(* Logix 5000 project; controller Soda_Ash vendor 1 type 14 code 92 rev 35.11; software revision 35.00 *)

TASK MainTask (continuous, watchdog 500 ms) : MainProgram, Simulation, Soda_Ash

MODULES
   Local : vendor 1 type 14 code 92 (ICP 5, rev 35.11)
      abclogixio3 : 1756-ENBT (ICP 9, Ethernet 131.151.52.140, rev 4.3)
         abclogixio2 : 1756-ENBT (Ethernet 131.151.52.139, rev 4.3, Output RPI 10 ms)
            CIP : vendor 1 type 14 code 92 (ICP 6, rev 20.1)
END_MODULES

TYPE Gate_Flop_Type :   // Flop Gate data
STRUCT
   Run_Status : BOOL;   // Run Status (1=running)
   Left_Status : BOOL;   // Left LS status (1=left position)
   Right_Status : BOOL;   // Right LS status (1=right position)
   Any_Fail : BOOL;   // Overall Failure Alarm (1= alarm)
   HOA_Fail : BOOL;   // HOA-switch-not-in-auto alarm (1-alarm)
   FTL_Fail : BOOL;   // Fail-to-divert-left failure alarm (1=alarm)
   FTR_Fail : BOOL;   // Fail-to-divert-right failure alarm (1=alarm)
   Seq_Left : BOOL;   // Gate open initiated from sequence
   Seq_Right : BOOL;   // Gate close initiated from sequence
END_STRUCT
END_TYPE

TYPE Gate_Slide_Type :   // Slide Gate data
STRUCT
   Run_Status : BOOL;   // Run Status (1=running)
   Open_Status : BOOL;   // Open LS status (1=open gate)
   Close_Status : BOOL;   // Close LS status (1=closed gate)
   Any_Fail : BOOL;   // Overall Failure Alarm (1= alarm)
   Aux_Fail : BOOL;   // Auxiliary failure alarm (1=alarm)
   OL_Fail : BOOL;   // Overload alarm (1=alarm)
   HOA_Fail : BOOL;   // HOA-switch-not-in-auto alarm (1-alarm)
   Seq_Open : BOOL;   // Gate open initiated from sequence
   Seq_Close : BOOL;   // Gate close initiated from sequence
END_STRUCT
END_TYPE

TYPE Motor_Conv_Type :   // Conveyor data
STRUCT
   Run_Status : BOOL;   // Run Status (1=running)
   Any_Fail : BOOL;   // Overall Failure Alarm (1= alarm)
   Aux_Fail : BOOL;   // Auxiliary failure alarm (1=alarm)
   SS_Fail : BOOL;   // Speed Switch failure alarm (1=alarm)
   OL_Fail : BOOL;   // Overload alarm (1=alarm)
   HOA_Fail : BOOL;   // HOA-switch-not-in-auto alarm (1-alarm)
   Seq_Start : BOOL;   // Motor start initiated from sequence
   Seq_Stop : BOOL;   // Motor stop initiated from sequence
END_STRUCT
END_TYPE

TYPE Motor_Std_Type :   // Motor data
STRUCT
   Run_Status : BOOL;   // Run Status (1=running)
   Any_Fail : BOOL;   // Overall Failure Alarm (1= alarm)
   Aux_Fail : BOOL;   // Auxiliary failure alarm (1=alarm)
   OL_Fail : BOOL;   // Overload alarm (1=alarm)
   HOA_Fail : BOOL;   // HOA-switch-not-in-auto alarm (1-alarm)
   Seq_Start : BOOL;   // Motor start initiated from sequence
   Seq_Stop : BOOL;   // Motor stop initiated from sequence
END_STRUCT
END_TYPE

TYPE Seq_Type :   // Sequence
STRUCT
   Step_Num : DINT;   // Current step number
   Running : BOOL;   // Running indication
   PC_Start : BOOL;   // Sequence start request from PC
   LTP_Start : BOOL;   // Sequence start request from LTP
   Ons : BOOL;   // One-shot storage to start
   Auto_Start : BOOL;   // Auto-start request
   Auto_Ons : BOOL;   // Auto-start one-shot storage
   Req_Tmr : TIMER;   // Auto-start hold timer
END_STRUCT
END_TYPE

TYPE Unit_Type :   // Common information for a unit
STRUCT
   Alm_Reset : BOOL;   // Alarm reset
   Local : BOOL;   // Local/remote control indication
   Maint : BOOL;   // Maintenance privilege for device control
   Man_StartOpen : BOOL;   // Manual start/open from operator
   Man_StopClose : BOOL;   // Manual stop/close from operator
   Man_DevNum : DINT;   // Number of device started/stopped at OI
   Msg : DINT;   // Message number
   Time_Remaining : DINT;   // Remaining time in timed steps
END_STRUCT
END_TYPE

TYPE Valve_Disc_Type :   // Discrete Valve data
STRUCT
   Open_Status : BOOL;   // Open LS status (1=open valve)
   Close_Status : BOOL;   // Close LS status (1=closed valve)
   Any_Fail : BOOL;   // Overall Failure Alarm (1= alarm)
   FTO_Fail : BOOL;   // Fail-to-open alarm (1=alarm)
   FTC_Fail : BOOL;   // Fail-to-close alarm (1=alarm)
   Seq_Open : BOOL;   // Valve open initiated from sequence
   Seq_Close : BOOL;   // Valve close initiated from sequence
END_STRUCT
END_TYPE

ADD_ON_INSTRUCTION Gate_Flop   (* revision 1.3 *)
// Flop gate control
// Revision note:
// Use CMP for device number
VAR_INPUT
   Left_LS : BOOL; {required}   // Gate-left limit switch physical input
   Right_LS : BOOL; {required}   // Gate-right limit switch physical input
   HOA_Switch : BOOL; {required}   // Hand-Off-Auto switch contact physical input (on when in Auto position)
   Alarm_Reset : BOOL; {required}   // Resets alarms
   Maint : BOOL; {required}   // Unit Maintenance/Operate Privilege
   Man_Left : BOOL; {required}   // Manual left for unit
   Man_Right : BOOL; {required}   // Manual right for unit
   Select_Dev_Num : DINT; {required}   // Number of device started/stopped at OI
   This_Dev_Num : DINT; {required}   // Number of this device for OI control
END_VAR
VAR_OUTPUT
   Sol_Left : BOOL; {access Read Only, required}   // Left position physical output
   Sol_Right : BOOL; {access Read Only, required}   // Right position physical output
END_VAR
VAR_IN_OUT
   Tag : Gate_Flop_Type; {required}   // Flop Gate Tag
END_VAR
VAR
   Left_Req : BOOL;   // Internal used for left logic
   Right_Req : BOOL;   // Internal used for right logic
   Fail_Tmr : TIMER := (PRE := 20000);   // Timer for alarms
END_VAR

ROUTINE Logic   (* ladder *)
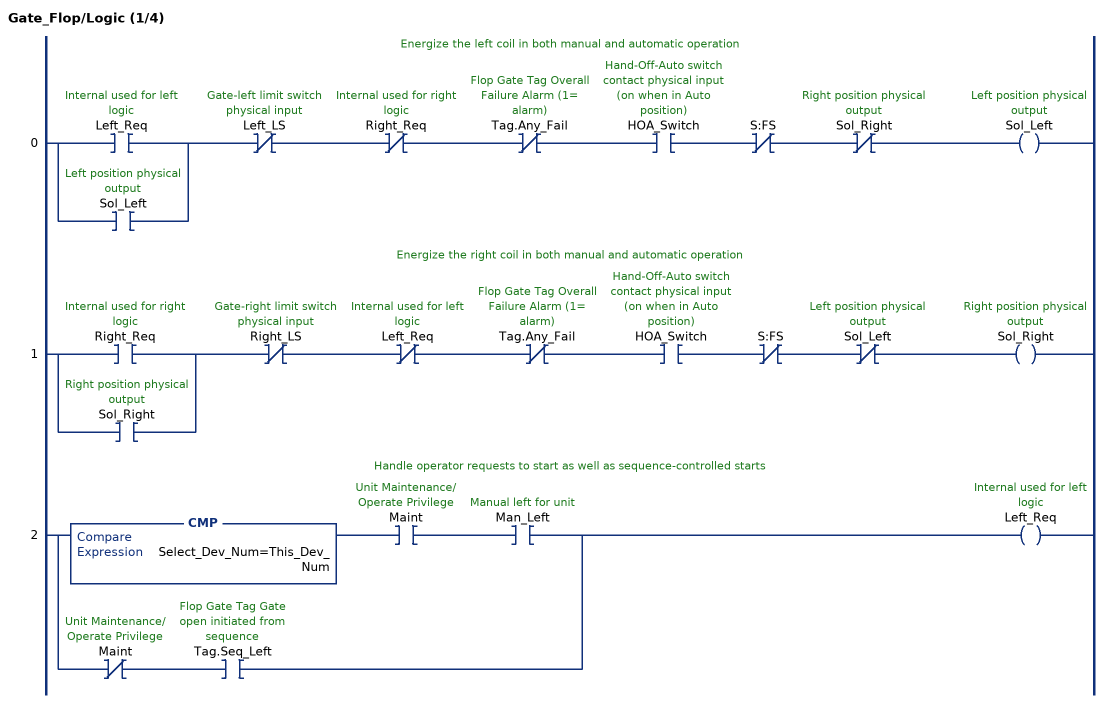
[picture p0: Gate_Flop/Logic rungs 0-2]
   // Energize the left coil in both manual and automatic operation
   0: [XIC(Left_Req) ,XIC(Sol_Left) ]XIO(Left_LS)XIO(Right_Req)XIO(Tag.Any_Fail)XIC(HOA_Switch)XIO(S:FS)XIO(Sol_Right)OTE(Sol_Left);
   // Energize the right coil in both manual and automatic operation
   1: [XIC(Right_Req) ,XIC(Sol_Right) ]XIO(Right_LS)XIO(Left_Req)XIO(Tag.Any_Fail)XIC(HOA_Switch)XIO(S:FS)XIO(Sol_Left)OTE(Sol_Right);
   // Handle operator requests to start as well as sequence-controlled starts
   2: [CMP(Select_Dev_Num=This_Dev_Num) XIC(Maint) XIC(Man_Left) ,XIO(Maint) XIC(Tag.Seq_Left) ]OTE(Left_Req);
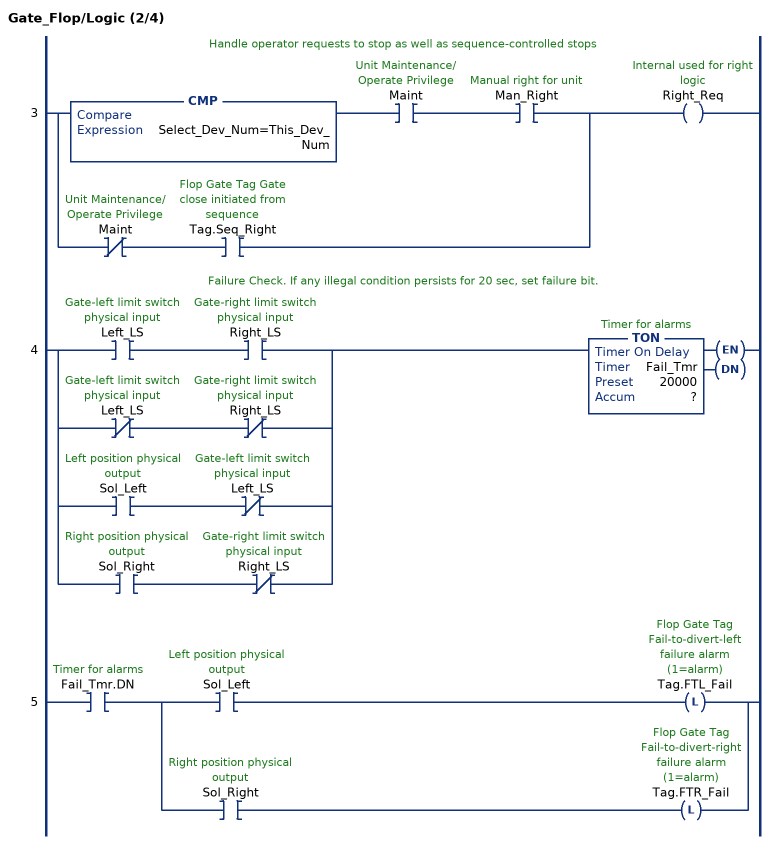
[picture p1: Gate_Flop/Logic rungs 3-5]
   // Handle operator requests to stop as well as sequence-controlled stops
   3: [CMP(Select_Dev_Num=This_Dev_Num) XIC(Maint) XIC(Man_Right) ,XIO(Maint) XIC(Tag.Seq_Right) ]OTE(Right_Req);
   // Failure Check. If any illegal condition persists for 20 sec, set failure bit.
   4: [XIC(Left_LS) XIC(Right_LS) ,XIO(Left_LS) XIO(Right_LS) ,XIC(Sol_Left) XIO(Left_LS) ,XIC(Sol_Right) XIO(Right_LS) ]TON(Fail_Tmr,?,?);
   5: XIC(Fail_Tmr.DN)[XIC(Sol_Left) OTL(Tag.FTL_Fail) ,XIC(Sol_Right) OTL(Tag.FTR_Fail) ];
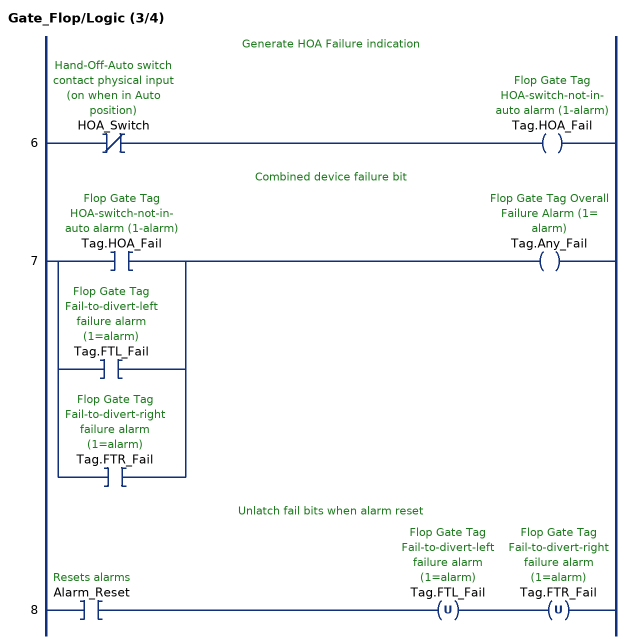
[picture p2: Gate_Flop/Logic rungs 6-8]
   // Generate HOA Failure indication
   6: XIO(HOA_Switch)OTE(Tag.HOA_Fail);
   // Combined device failure bit
   7: [XIC(Tag.HOA_Fail) ,XIC(Tag.FTL_Fail) ,XIC(Tag.FTR_Fail) ]OTE(Tag.Any_Fail);
   // Unlatch fail bits when alarm reset
   8: XIC(Alarm_Reset)OTU(Tag.FTL_Fail)OTU(Tag.FTR_Fail);
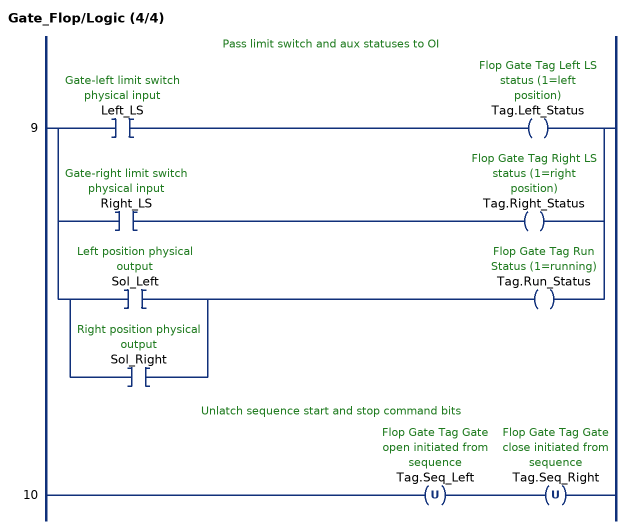
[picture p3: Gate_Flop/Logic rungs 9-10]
   // Pass limit switch and aux statuses to OI
   9: [XIC(Left_LS) OTE(Tag.Left_Status) ,XIC(Right_LS) OTE(Tag.Right_Status) ,[XIC(Sol_Left) ,XIC(Sol_Right) ] OTE(Tag.Run_Status) ];
   // Unlatch sequence start and stop command bits
   10: OTU(Tag.Seq_Left)OTU(Tag.Seq_Right);
END_ROUTINE
END_ADD_ON_INSTRUCTION

ADD_ON_INSTRUCTION Gate_Slide   (* revision 1.3 *)
// Slide gate control
// Revision note:
// Correct name of "Dev_Num" input parameters
VAR_INPUT
   Open_Aux : BOOL; {required}   // Open auxillary contact physical input
   Close_Aux : BOOL; {required}   // Close auxiliary contact physical input
   OL_Trip : BOOL; {required}   // Overload trip contact physical input
   HOA_Switch : BOOL; {required}   // Hand-Off-Auto switch contact physical input (on when in Auto position)
   Open_LS : BOOL; {required}   // Gate-open limit switch physical input
   Close_LS : BOOL; {required}   // Gate-closed limit switch physical input
   Alarm_Reset : BOOL; {required}   // Resets alarms
   Maint : BOOL; {required}   // Unit Maintenance/Operate Privilege
   Man_Open : BOOL; {required}   // Manual open for unit
   Man_Close : BOOL; {required}   // Manual close for unit
   Select_Dev_Num : DINT; {required}   // Number of device started/stopped at OI
   This_Dev_Num : DINT; {required}   // Number of this device for OI control
END_VAR
VAR_OUTPUT
   Start_Open : BOOL; {access Read Only, required}   // Open motor starter contact physical input
   Start_Close : BOOL; {access Read Only, required}   // Close motor starter contact physical input
END_VAR
VAR_IN_OUT
   Tag : Gate_Slide_Type; {required}   // Slide Gate Tag
END_VAR
VAR
   Open_Req : BOOL;   // Internal used for open logic
   Close_Req : BOOL;   // Internal used for close logic
   Fail_Tmr : TIMER := (PRE := 20000);   // Timer for aux-fail alarm
END_VAR

ROUTINE Logic   (* ladder *)
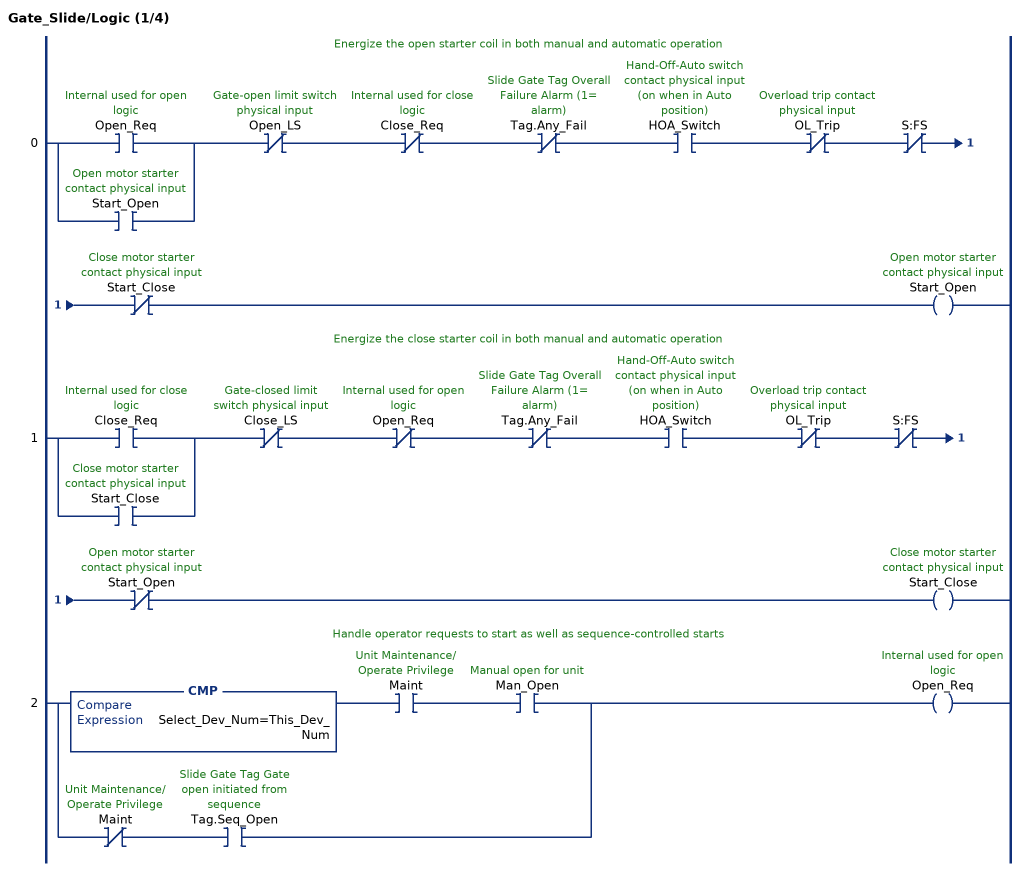
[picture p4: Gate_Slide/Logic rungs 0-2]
   // Energize the open starter coil in both manual and automatic operation
   0: [XIC(Open_Req) ,XIC(Start_Open) ]XIO(Open_LS)XIO(Close_Req)XIO(Tag.Any_Fail)XIC(HOA_Switch)XIO(OL_Trip)XIO(S:FS)XIO(Start_Close)OTE(Start_Open);
   // Energize the close starter coil in both manual and automatic operation
   1: [XIC(Close_Req) ,XIC(Start_Close) ]XIO(Close_LS)XIO(Open_Req)XIO(Tag.Any_Fail)XIC(HOA_Switch)XIO(OL_Trip)XIO(S:FS)XIO(Start_Open)OTE(Start_Close);
   // Handle operator requests to start as well as sequence-controlled starts
   2: [CMP(Select_Dev_Num=This_Dev_Num) XIC(Maint) XIC(Man_Open) ,XIO(Maint) XIC(Tag.Seq_Open) ]OTE(Open_Req);
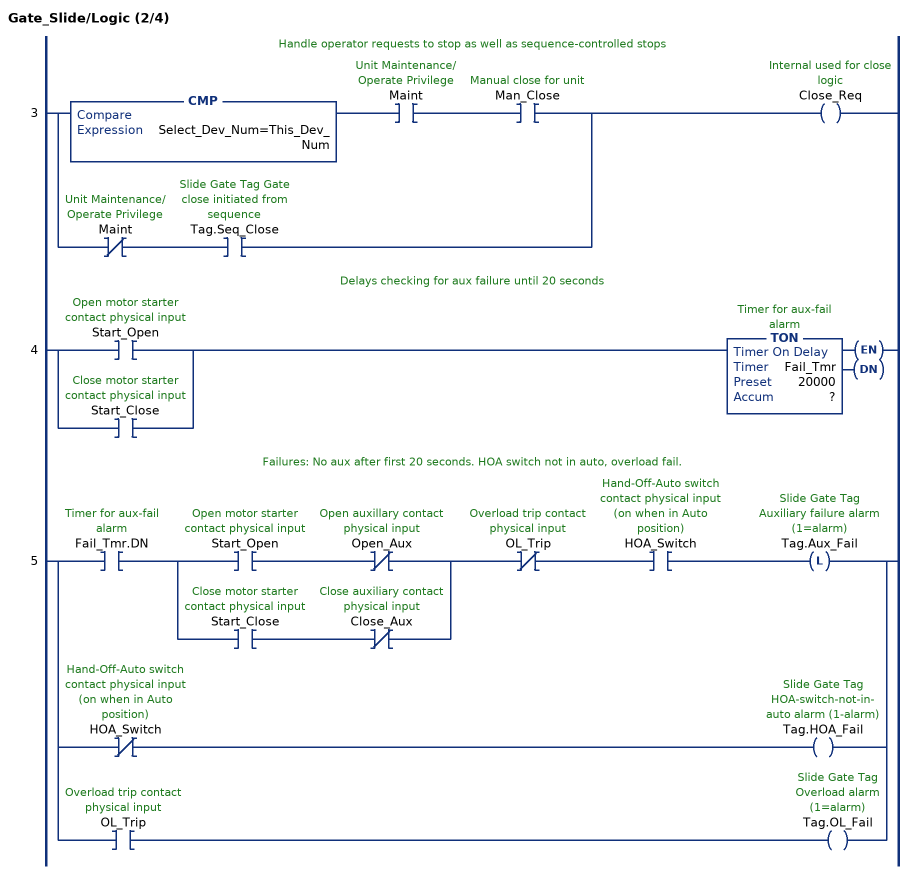
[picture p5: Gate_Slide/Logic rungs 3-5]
   // Handle operator requests to stop as well as sequence-controlled stops
   3: [CMP(Select_Dev_Num=This_Dev_Num) XIC(Maint) XIC(Man_Close) ,XIO(Maint) XIC(Tag.Seq_Close) ]OTE(Close_Req);
   // Delays checking for aux failure until 20 seconds
   4: [XIC(Start_Open) ,XIC(Start_Close) ]TON(Fail_Tmr,?,?);
   // Failures: No aux after first 20 seconds. HOA switch not in auto, overload fail.
   5: [XIC(Fail_Tmr.DN) [XIC(Start_Open) XIO(Open_Aux) ,XIC(Start_Close) XIO(Close_Aux) ] XIO(OL_Trip) XIC(HOA_Switch) OTL(Tag.Aux_Fail) ,XIO(HOA_Switch) OTE(Tag.HOA_Fail) ,XIC(OL_Trip) OTE(Tag.OL_Fail) ];
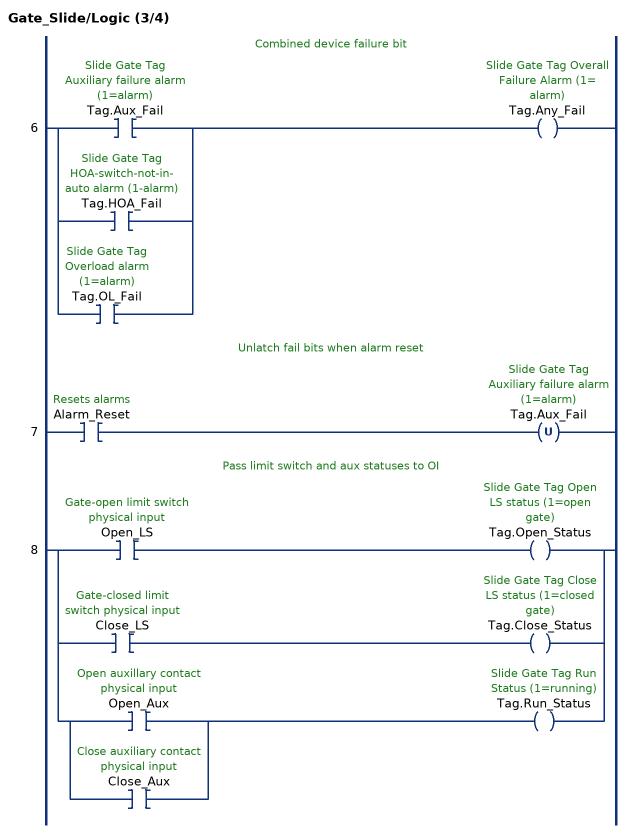
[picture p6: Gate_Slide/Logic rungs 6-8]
   // Combined device failure bit
   6: [XIC(Tag.Aux_Fail) ,XIC(Tag.HOA_Fail) ,XIC(Tag.OL_Fail) ]OTE(Tag.Any_Fail);
   // Unlatch fail bits when alarm reset
   7: XIC(Alarm_Reset)OTU(Tag.Aux_Fail);
   // Pass limit switch and aux statuses to OI
   8: [XIC(Open_LS) OTE(Tag.Open_Status) ,XIC(Close_LS) OTE(Tag.Close_Status) ,[XIC(Open_Aux) ,XIC(Close_Aux) ] OTE(Tag.Run_Status) ];
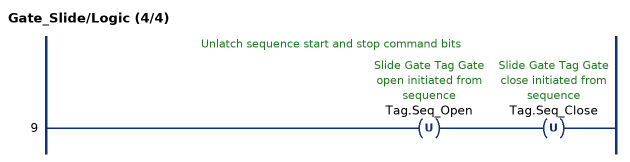
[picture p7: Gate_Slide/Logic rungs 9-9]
   // Unlatch sequence start and stop command bits
   9: OTU(Tag.Seq_Open)OTU(Tag.Seq_Close);
END_ROUTINE
END_ADD_ON_INSTRUCTION

ADD_ON_INSTRUCTION Motor_Conv   (* revision 1.3 *)
// Conveyor motor control
VAR_INPUT
   Aux_Contact : BOOL; {required}   // Auxillary contact physical input
   OL_Trip : BOOL; {required}   // Overload trip contact physical input
   HOA_Switch : BOOL; {required}   // Hand-Off-Auto switch contact physical input (on when in Auto position)
   Speed_Switch : BOOL; {required}   // Speed Switch physical input (1=running)
   Alarm_Reset : BOOL; {required}   // Resets alarms
   Maint : BOOL; {required}   // Unit Maintenance/Operate Privilege
   Man_Start : BOOL; {required}   // Manual start for unit
   Man_Stop : BOOL; {required}   // Manual stop for unit
   Select_Dev_Num : DINT; {required}   // Number of device started/stopped at OI
   This_Dev_Num : DINT; {required}   // Number of this device for OI control
END_VAR
VAR_OUTPUT
   Starter : BOOL; {access Read Only, required}   // Motor starter contact physical input
END_VAR
VAR_IN_OUT
   Tag : Motor_Conv_Type; {required}   // Motor Tag
END_VAR
VAR
   Start_Req : BOOL;   // Internal used for start logic
   Stop_Req : BOOL;   // Internal used for stop logic
   Fail_Tmr : TIMER := (PRE := 40000);   // Timer for aux-fail alarm
   SS_Fail_Tmr : TIMER := (PRE := 20000);   // Timer for Speed switch fail alarm
END_VAR

ROUTINE Logic   (* ladder *)
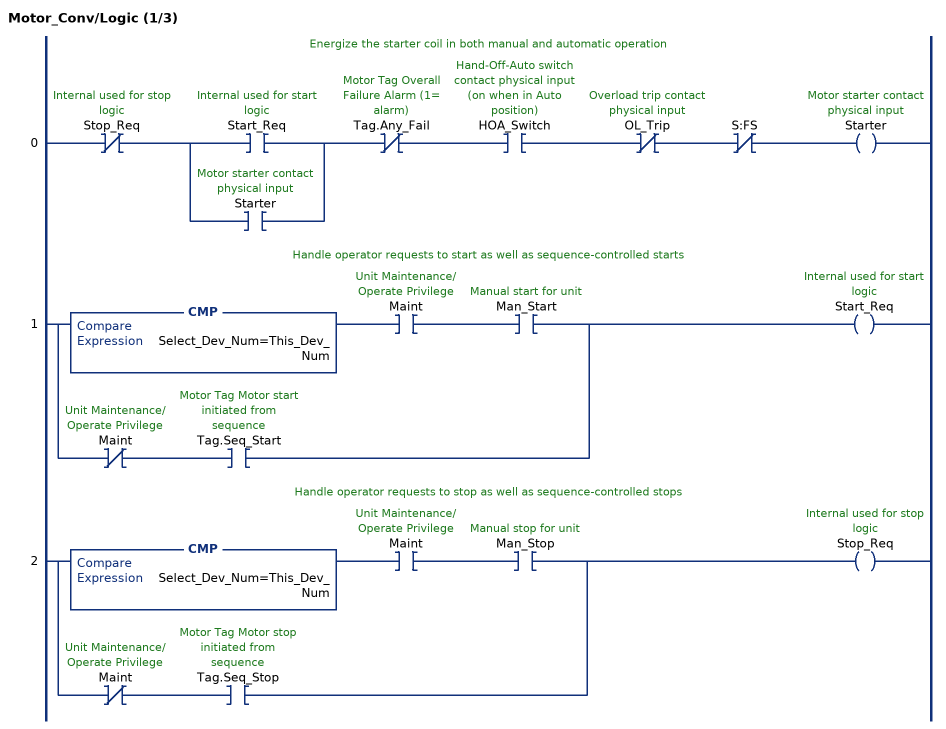
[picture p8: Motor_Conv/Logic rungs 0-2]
   // Energize the starter coil in both manual and automatic operation
   0: XIO(Stop_Req)[XIC(Start_Req) ,XIC(Starter) ]XIO(Tag.Any_Fail)XIC(HOA_Switch)XIO(OL_Trip)XIO(S:FS)OTE(Starter);
   // Handle operator requests to start as well as sequence-controlled starts
   1: [CMP(Select_Dev_Num=This_Dev_Num) XIC(Maint) XIC(Man_Start) ,XIO(Maint) XIC(Tag.Seq_Start) ]OTE(Start_Req);
   // Handle operator requests to stop as well as sequence-controlled stops
   2: [CMP(Select_Dev_Num=This_Dev_Num) XIC(Maint) XIC(Man_Stop) ,XIO(Maint) XIC(Tag.Seq_Stop) ]OTE(Stop_Req);
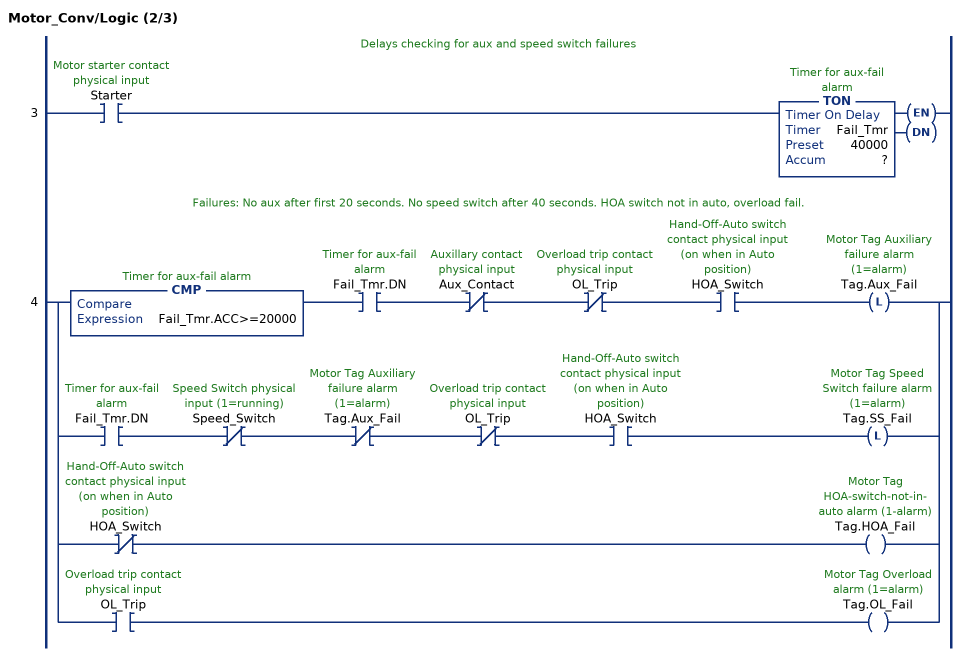
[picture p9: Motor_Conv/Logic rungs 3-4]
   // Delays checking for aux and speed switch failures
   3: XIC(Starter)TON(Fail_Tmr,?,?);
   // Failures: No aux after first 20 seconds. No speed switch after 40 seconds. HOA switch not in auto, overload fail.
   4: [CMP(Fail_Tmr.ACC>=20000) XIC(Fail_Tmr.DN) XIO(Aux_Contact) XIO(OL_Trip) XIC(HOA_Switch) OTL(Tag.Aux_Fail) ,XIC(Fail_Tmr.DN) XIO(Speed_Switch) XIO(Tag.Aux_Fail) XIO(OL_Trip) XIC(HOA_Switch) OTL(Tag.SS_Fail) ,XIO(HOA_Switch) OTE(Tag.HOA_Fail) ,XIC(OL_Trip) OTE(Tag.OL_Fail) ];
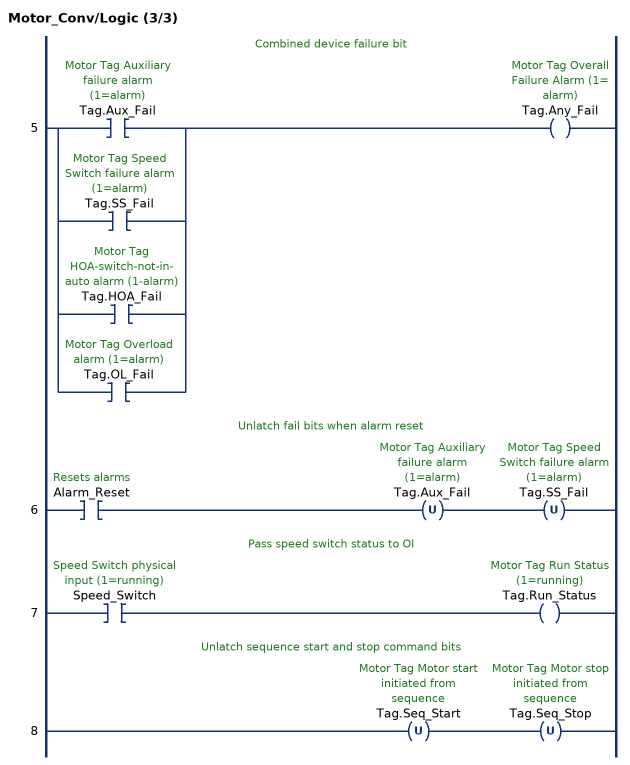
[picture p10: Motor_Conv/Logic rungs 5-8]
   // Combined device failure bit
   5: [XIC(Tag.Aux_Fail) ,XIC(Tag.SS_Fail) ,XIC(Tag.HOA_Fail) ,XIC(Tag.OL_Fail) ]OTE(Tag.Any_Fail);
   // Unlatch fail bits when alarm reset
   6: XIC(Alarm_Reset)OTU(Tag.Aux_Fail)OTU(Tag.SS_Fail);
   // Pass speed switch status to OI
   7: XIC(Speed_Switch)OTE(Tag.Run_Status);
   // Unlatch sequence start and stop command bits
   8: OTU(Tag.Seq_Start)OTU(Tag.Seq_Stop);
END_ROUTINE
END_ADD_ON_INSTRUCTION

ADD_ON_INSTRUCTION Motor_Std   (* revision 1.3 *)
// Standard motor control
VAR_INPUT
   Aux_Contact : BOOL; {required}   // Auxillary contact physical input
   OL_Trip : BOOL; {required}   // Overload trip contact physical input
   HOA_Switch : BOOL; {required}   // Hand-Off-Auto switch contact physical input (on when in Auto position)
   Alarm_Reset : BOOL; {required}   // Resets alarms
   Maint : BOOL; {required}   // Unit Maintenance/Operate Privilege
   Man_Start : BOOL; {required}   // Manual start for unit
   Man_Stop : BOOL; {required}   // Manual stop for unit
   Select_Dev_Num : DINT; {required}   // Number of device started/stopped at OI
   This_Dev_Num : DINT; {required}   // Number of this device for OI control
END_VAR
VAR_OUTPUT
   Starter : BOOL; {access Read Only, required}   // Motor starter contact physical input
END_VAR
VAR_IN_OUT
   Tag : Motor_Std_Type; {required}   // Motor Tag
END_VAR
VAR
   Start_Req : BOOL;   // Internal used for start logic
   Stop_Req : BOOL;   // Internal used for stop logic
   Fail_Tmr : TIMER := (PRE := 20000);   // Timer for aux-fail alarm
END_VAR

ROUTINE Logic   (* ladder *)
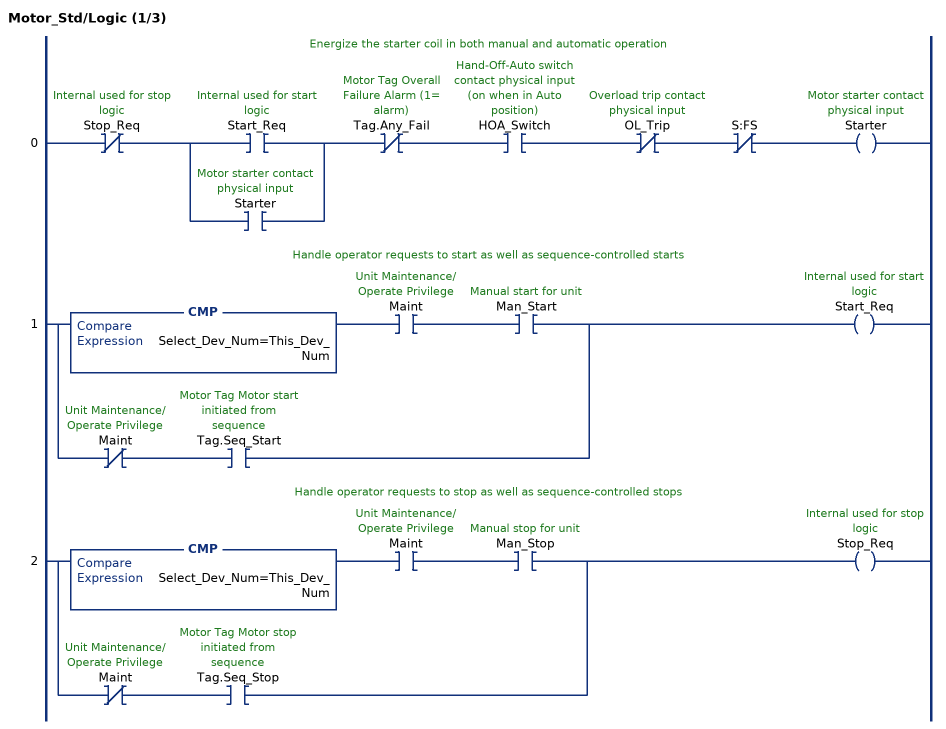
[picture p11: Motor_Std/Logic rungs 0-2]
   // Energize the starter coil in both manual and automatic operation
   0: XIO(Stop_Req)[XIC(Start_Req) ,XIC(Starter) ]XIO(Tag.Any_Fail)XIC(HOA_Switch)XIO(OL_Trip)XIO(S:FS)OTE(Starter);
   // Handle operator requests to start as well as sequence-controlled starts
   1: [CMP(Select_Dev_Num=This_Dev_Num) XIC(Maint) XIC(Man_Start) ,XIO(Maint) XIC(Tag.Seq_Start) ]OTE(Start_Req);
   // Handle operator requests to stop as well as sequence-controlled stops
   2: [CMP(Select_Dev_Num=This_Dev_Num) XIC(Maint) XIC(Man_Stop) ,XIO(Maint) XIC(Tag.Seq_Stop) ]OTE(Stop_Req);
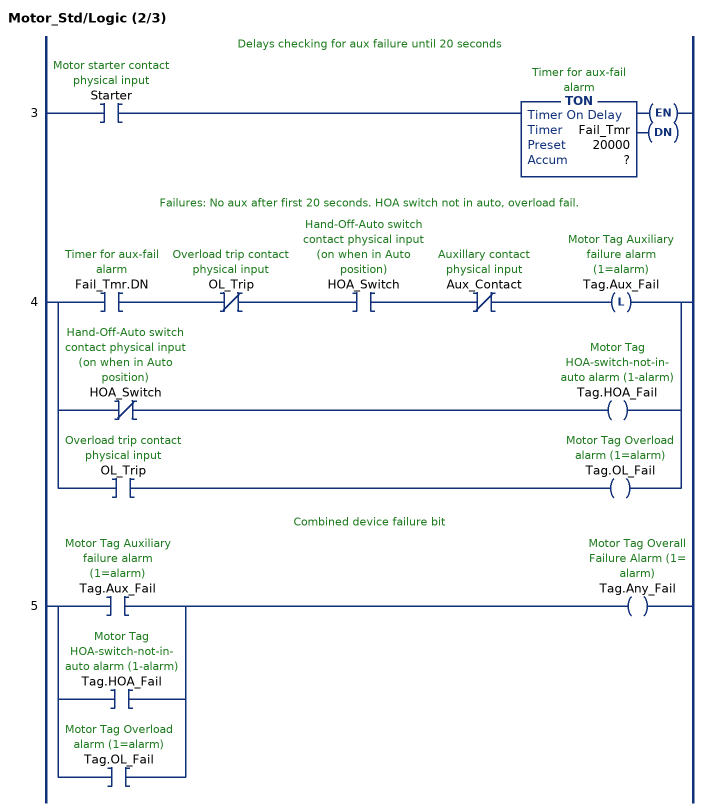
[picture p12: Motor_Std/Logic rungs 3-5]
   // Delays checking for aux failure until 20 seconds
   3: XIC(Starter)TON(Fail_Tmr,?,?);
   // Failures: No aux after first 20 seconds. HOA switch not in auto, overload fail.
   4: [XIC(Fail_Tmr.DN) XIO(OL_Trip) XIC(HOA_Switch) XIO(Aux_Contact) OTL(Tag.Aux_Fail) ,XIO(HOA_Switch) OTE(Tag.HOA_Fail) ,XIC(OL_Trip) OTE(Tag.OL_Fail) ];
   // Combined device failure bit
   5: [XIC(Tag.Aux_Fail) ,XIC(Tag.HOA_Fail) ,XIC(Tag.OL_Fail) ]OTE(Tag.Any_Fail);
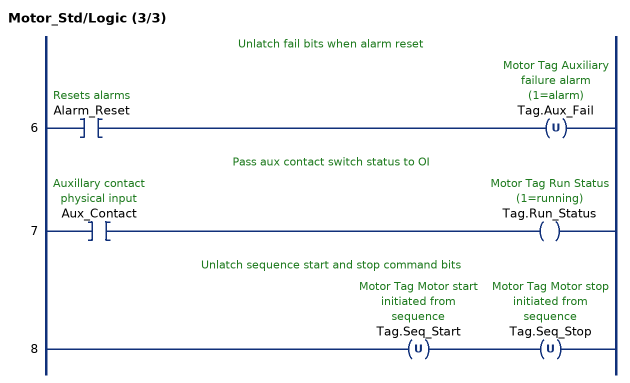
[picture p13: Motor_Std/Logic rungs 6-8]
   // Unlatch fail bits when alarm reset
   6: XIC(Alarm_Reset)OTU(Tag.Aux_Fail);
   // Pass aux contact switch status to OI
   7: XIC(Aux_Contact)OTE(Tag.Run_Status);
   // Unlatch sequence start and stop command bits
   8: OTU(Tag.Seq_Start)OTU(Tag.Seq_Stop);
END_ROUTINE
END_ADD_ON_INSTRUCTION

ADD_ON_INSTRUCTION Valve_Disc   (* revision 1.5 *)
// Discrete Valve Control
// Revision note:
// Correct name of "Dev_Num" input parameters
VAR_INPUT
   Open_LS : BOOL; {required}   // Valve-Open limit switch
   Close_LS : BOOL; {required}   // Valve-Closed limit switch
   Alarm_Reset : BOOL; {required}   // Resets alarms
   Maint : BOOL; {required}   // Unit Maintenance/Operate Privilege
   Man_Open : BOOL; {required}   // Manual start/open for unit
   Man_Close : BOOL; {required}   // Manual stop/close for unit
   Select_Dev_Num : DINT; {required}   // Number of device started/stopped at OI
   This_Dev_Num : DINT; {required}   // Number of this device for OI control
END_VAR
VAR_OUTPUT
   Vlv_Sol : BOOL; {access Read Only, required}   // Valve solenoid (1=open, 0=close)
END_VAR
VAR_IN_OUT
   Tag : Valve_Disc_Type; {required}   // Valve Tag
END_VAR
VAR
   Fail_Tmr : TIMER := (PRE := 20000);   // Timer for alarms
END_VAR

ROUTINE Logic   (* ladder *)
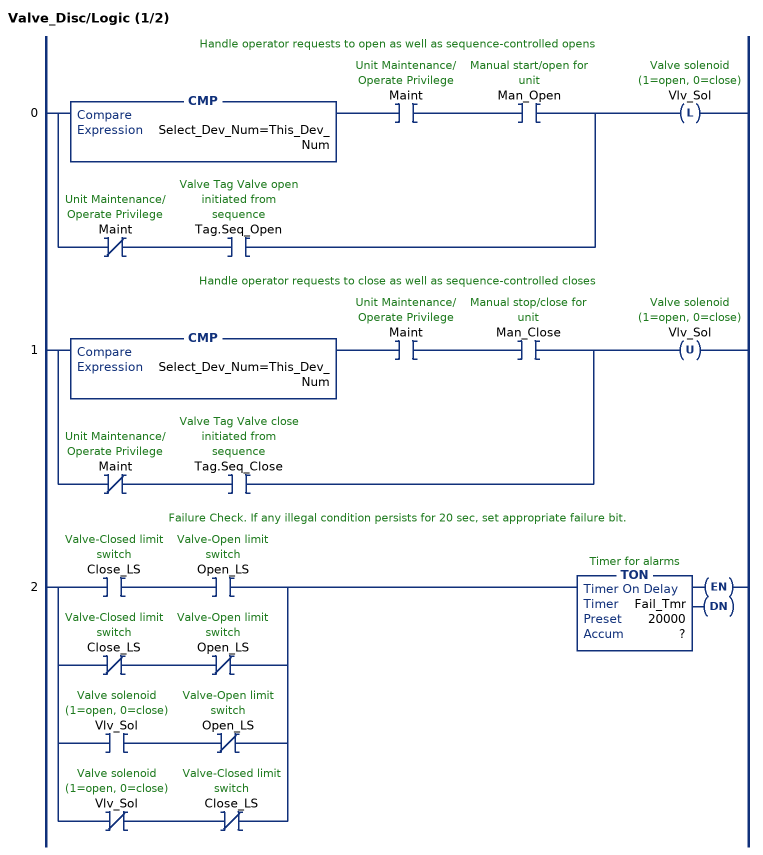
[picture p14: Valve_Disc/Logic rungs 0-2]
   // Handle operator requests to open as well as sequence-controlled opens
   0: [CMP(Select_Dev_Num=This_Dev_Num) XIC(Maint) XIC(Man_Open) ,XIO(Maint) XIC(Tag.Seq_Open) ]OTL(Vlv_Sol);
   // Handle operator requests to close as well as sequence-controlled closes
   1: [CMP(Select_Dev_Num=This_Dev_Num) XIC(Maint) XIC(Man_Close) ,XIO(Maint) XIC(Tag.Seq_Close) ]OTU(Vlv_Sol);
   // Failure Check. If any illegal condition persists for 20 sec, set appropriate failure bit.
   2: [XIC(Close_LS) XIC(Open_LS) ,XIO(Close_LS) XIO(Open_LS) ,XIC(Vlv_Sol) XIO(Open_LS) ,XIO(Vlv_Sol) XIO(Close_LS) ]TON(Fail_Tmr,?,?);
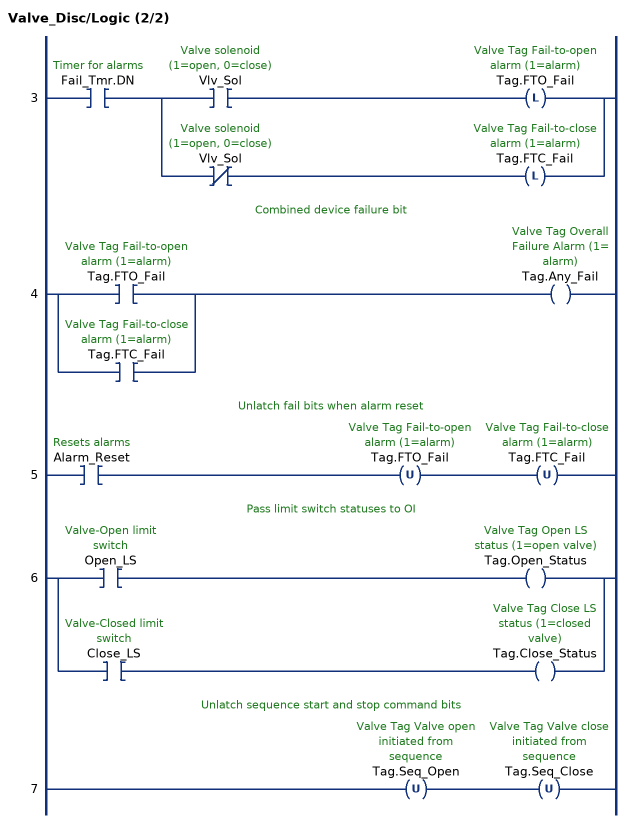
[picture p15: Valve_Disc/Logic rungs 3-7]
   3: XIC(Fail_Tmr.DN)[XIC(Vlv_Sol) OTL(Tag.FTO_Fail) ,XIO(Vlv_Sol) OTL(Tag.FTC_Fail) ];
   // Combined device failure bit
   4: [XIC(Tag.FTO_Fail) ,XIC(Tag.FTC_Fail) ]OTE(Tag.Any_Fail);
   // Unlatch fail bits when alarm reset
   5: XIC(Alarm_Reset)OTU(Tag.FTO_Fail)OTU(Tag.FTC_Fail);
   // Pass limit switch statuses to OI
   6: [XIC(Open_LS) OTE(Tag.Open_Status) ,XIC(Close_LS) OTE(Tag.Close_Status) ];
   // Unlatch sequence start and stop command bits
   7: OTU(Tag.Seq_Open)OTU(Tag.Seq_Close);
END_ROUTINE
END_ADD_ON_INSTRUCTION

VAR_GLOBAL   (* controller tags *)
   Alarm_Reset : BOOL;   // PC Alarm Reset
   C6100 : Motor_Conv_Type;   // C-6100 Soda Ash Screw Conveyor
   C6100_Aux : BOOL;   // C-6100 Soda Ash Screw Conveyor Aux. Contact
   C6100_DB : Motor_Conv := (HOA_Switch := 1, This_Dev_Num := 1);   // C-6100 Soda Ash Screw Conveyor
   C6100_FailESdwn_Tmr : TIMER := (PRE := 1000);   // C-6100 Soda Ash Screw Conveyor Fail to Eshutfown Timer
   C6100_FailHold_Tmr : TIMER := (PRE := 1000); {produced}   // C-6100 Soda Ash Screw Conveyor Fail to Eshutfown Timer
   C6100_FailWSdwn_Tmr : TIMER := (PRE := 1000);   // C-6100 Soda Ash Screw Conveyor Fail to Eshutfown Timer
   C6100_HOA : BOOL := 1;   // C-6100 Storage Pump Screw Conveyor H.O.A.
   C6100_OL : BOOL;   // C-6100 Soda Ash Screw Conveyor O. L. Trip
   C6100_Start : BOOL;   // C-6100 Soda Ash Screw Conveyor Starter
   CIP_Export_Info : DINT := 17412;
   CIP_msg : MESSAGE;
        MessageParameters(ServiceCode := 16#004c, LocalElement := CIP_Export_Info, ...)
   CIP_Start_Request : BOOL;   // Soda Ash Start Transfer Request from CIP
   Convey_Time : TIMER := (PRE := 30000);   // Soda Ash C-6100 Conveyor Clear Timer
   FIC1000 : PID := (CTL := 8393600, PE := 1, OLH := 1, DVPA := 1, PVLA := 1, PVHA := 1, SP := 50.0, KP := 1.0, KI := 0.1, MAXS := 200.0, SO := 100.0, MAXO := 100.0, UPD := 1.0, ERR := 50.0, OUT := 100.0, MAXI := 100.0, MAXCV := 100.0, MAXTIE := 100.0, DATA[3] := 50.0, DATA[4] := 50.0, DATA[5] := 1.0, DATA[6] := 1.0, DATA[7] := 16.0, DATA[8] := 2.0, DATA[9] := 0.05, DATA[11] := 2.0, DATA[12] := 0.05, DATA[15] := 1.0, DATA[16] := 1.0);   // Soda Ash FIC1000 Sample Flow Controller
   FIC1000_Tmr : TIMER := (PRE := 1000);   // Soda Ash FIC1000 Material A Flow Controller Sample Timer
   FQI1000 : DINT := 32;   // Soda Ash FQI1000 Sample Flow Accumulation
   FQI1000_Oper_Reset : BOOL;   // Soda Ash FQI1000 Sample Flow Accumulation Reset
   FQI1000_Tmr : TIMER := (PRE := 1000);   // Soda Ash FQI1000 Sample Flow Accumulation Timer
   FT1000 : REAL := 100.0;   // Soda Ash FT1000 Sample Flow
   FY1000 : REAL := 100.0;   // Soda Ash FY1000 Sample Flow Control Valve
   G6000 : Gate_Slide_Type := (Close_Status := 1);   // G-6000 CIP Tank Slide Gate
   G6000_Aux : BOOL;   // G-6000 CIP Tank Slide Gate Aux. Contact
   G6000_Close_Aux : BOOL;   // G-6000 CIP Tank Slide Gate Clos Aux Contact
   G6000_DB : Gate_Slide := (HOA_Switch := 1, Close_LS := 1, This_Dev_Num := 2);   // G-6000 CIP Tank Slide Gate
   G6000_FailESdwn_Tmr : TIMER := (PRE := 1000);   // G-6000 CIP Tank Slide Gate Fail to Eshutdown Timer
   G6000_FailHold_Tmr : TIMER := (PRE := 1000); {produced}   // G-6000 CIP Tank Slide Gate Fail to Eshutdown Timer
   G6000_HOA : BOOL := 1;   // G-6000 CIP Tank Slide Gate H.O.A.
   G6000_OL : BOOL;   // G-6000 CIP Tank Slide Gate O. L. Trip
   G6000_Open_Aux : BOOL;   // G-6000 CIP Tank Slide Gate Open Aux Contact
   G6000_Start_Close : BOOL;   // G-6000 CIP Tank Slide Gate Starter Close
   G6000_Start_Open : BOOL;   // G-6000 CIP Tank Slide Gate Starter Open
   G6200 : Gate_Flop_Type := (Right_Status := 1);   // G-6200 CIP Tank Flop Gate
   G6200_DB : Gate_Flop := (Right_LS := 1, HOA_Switch := 1, This_Dev_Num := 4);   // G-6200 CIP Tank Flop Gate
   G6200_Fail_Tmr : TIMER := (PRE := 20000);   // G-6200 CIP Tank Flop Gate Fail Timer
   G6200_HOA : BOOL := 1;   // G-6200 Soda Ash CIP flop Gate H.O.A.
   G6200_Sol_Left : BOOL;   // G-6200 CIP Tank Flop Gate Left Valve
   G6200_Sol_Right : BOOL;   // G-6200 CIP Tank Flop Gate Right Valve
   Junk : INT;
   L6100 : Motor_Std_Type;   // L-6100 Soda Ash Airlock
   L6100_Aux : BOOL;   // L-6100 Soda Ash Airlock Aux. Contact
   L6100_DB : Motor_Std := (HOA_Switch := 1, This_Dev_Num := 3);   // L-6100 Soda Ash Airlock
   L6100_FailHold_Tmr : TIMER := (PRE := 1000); {produced}   // L-6100 Soda Ash Airlock Fail to Shutdown Timer
   L6100_FailSdwn_Tmr : TIMER := (PRE := 1000);   // L-6100 Soda Ash Airlock Fail to Shutdown Timer
   L6100_HOA : BOOL := 1;   // L-6100 Storage Aitlock Motor H.O.A.
   L6100_Level_Alarm_Tmr : TIMER := (PRE := 2000);   // L-6100 Low Bin Indicator Alarm Timer
   L6100_Level_ESdwn_Tmr : TIMER := (PRE := 20000);   // L6100 low level when Transfer Running Shutdown Timer
   L6100_Level_Sdwn_Tmr : TIMER := (PRE := 20000);   // L6100 low level when Transfer Running Shutdown Timer
   L6100_Level_Shutdown_Tmr : TIMER := (PRE := 20000);   // L6100 low level shutdown Timer
   L6100_OL : BOOL;   // L-6100 Soda Ash Airlock O. L. Trip
   L6100_Start : BOOL;   // L-6100 Soda Ash Airlock Starter
   LSL6100 : BOOL;   // B-6000 Soda Ash Tank Low Level Switch
   LSL6100_Alarm : BOOL;   // Soda Ash L-6100 Low Bin Indicator Alarm
   Soda_Ash : Unit_Type;   // Soda Ash Unit
   Soda_Ash_EShutdown : Seq_Type := (Req_Tmr.PRE := 5000);   // Soda Ash E-Shutdown
   Soda_Ash_EShutdown_Tmr : TIMER := (PRE := 15000);   // Soda Ash B-6000 E-Shutdown In Progress Timer
   Soda_Ash_Export_Info : DINT;   // Soda Ash Export Info For other units
   Soda_Ash_Hold : Seq_Type := (Req_Tmr.PRE := 5000);   // Soda Ash Hold
   Soda_Ash_In_Shutdown_EShut : ALIAS FOR Soda_Ash_Export_Info.2;
   Soda_Ash_Sdwn_from_CIP : ALIAS FOR CIP_Export_Info.11;   // Soda Ash Shutdown Request From CIP
   Soda_Ash_Shutdown : Seq_Type := (Req_Tmr.PRE := 5000);   // Soda Ash Shutdown
   Soda_Ash_Shutdown_Complete : ALIAS FOR Soda_Ash_Export_Info.1;   // Soda Ash Shutdown Status To CIP
   Soda_Ash_Start_from_CIP : ALIAS FOR CIP_Export_Info.12;   // Soda Ash Start Transfer Request From CIP
   Soda_Ash_StrtTrans : Seq_Type := (Req_Tmr.PRE := 5000);   // Soda Ash Start Transfer
   Soda_Ash_Transfer_Running : ALIAS FOR Soda_Ash_Export_Info.0;   // Soda Ash Transfer Status To CIP
   SodaAsh : Unit_Type;
   SS6100 : BOOL;   // C-6100 Soda Ash Screw Conveyor Zero Speed Switch
   SS6100_Alarm : BOOL;   // SS6100 Speed switch off when running alarm
   SS6100_Fail_Tmr : TIMER := (PRE := 5000);   // SS6100 Soda Ash Screw Conveyor Failure Timer
   SS6100_Off_ESdwn_Tmr : TIMER := (PRE := 2000);   // SS6100 off when Transfer Running EShutdown Timer
   XV1001 : Valve_Disc_Type := (Close_Status := 1);   // XV1001 Soda Ash Outlet Valve
   XV1001_CloseLS : BOOL := 1;   // XV1001 Soda Ash Outlet Valve Closed Limit Switch
   XV1001_DB : Valve_Disc := (Close_LS := 1, This_Dev_Num := 5);   // XV1001 Soda Ash Outlet Valve
   XV1001_FailHold_Tmr : TIMER := (PRE := 1000);   // XV1001 Soda Ash Outlet Valve Fail to Hold Timer
   XV1001_OpenLS : BOOL;   // XV1001 Soda Ash Outlet Valve Open Limit Switch
   XV1001_Sol_Vlv : BOOL;   // XV1001 Soda Ash Outlet Valve Solenoid
   XV6002_Closed : ALIAS FOR CIP_Export_Info.5;
   ZSC6000 : BOOL := 1;   // G-6000 Soda Ash CIP Slide Gate Closed LS
   ZSL6200 : BOOL;   // G-6200 Soda Ash CIP flop Gate Left LS
   ZSO6000 : BOOL;   // G-6000 Soda Ash CIP Slide Gate Open LS
   ZSR6200 : BOOL := 1;   // G-6200 Soda Ash CIP flop Gate Right LS
END_VAR

PROGRAM MainProgram   (* main routine Communications *)
VAR
   msg_tmr : TIMER := (PRE := 2000);
END_VAR

ROUTINE Communications   (* ladder *)
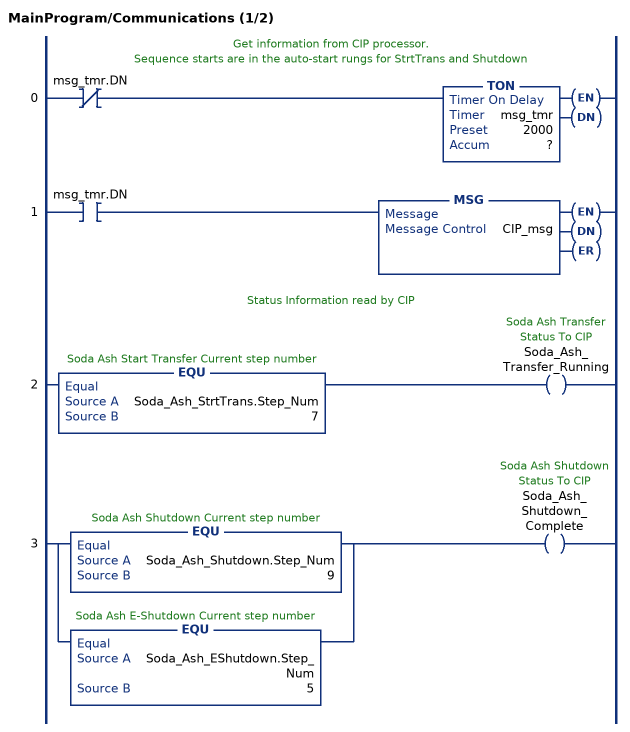
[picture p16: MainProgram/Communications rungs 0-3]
   // Get information from CIP processor.
   // Sequence starts are in the auto-start rungs for StrtTrans and Shutdown
   0: XIO(msg_tmr.DN)TON(msg_tmr,?,?);
   1: XIC(msg_tmr.DN)MSG(CIP_msg);
   // Status Information read by CIP
   2: EQU(Soda_Ash_StrtTrans.Step_Num,7)OTE(Soda_Ash_Transfer_Running);
   3: [EQU(Soda_Ash_Shutdown.Step_Num,9) ,EQU(Soda_Ash_EShutdown.Step_Num,5) ]OTE(Soda_Ash_Shutdown_Complete);
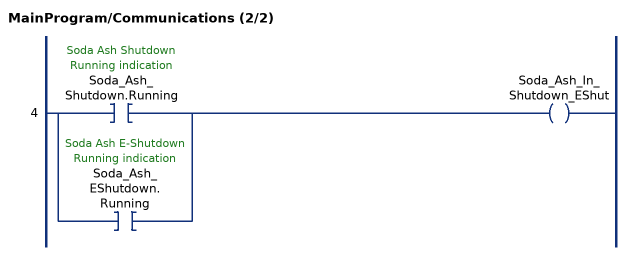
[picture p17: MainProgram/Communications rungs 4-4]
   4: [XIC(Soda_Ash_Shutdown.Running) ,XIC(Soda_Ash_EShutdown.Running) ]OTE(Soda_Ash_In_Shutdown_EShut);
END_ROUTINE
END_PROGRAM
